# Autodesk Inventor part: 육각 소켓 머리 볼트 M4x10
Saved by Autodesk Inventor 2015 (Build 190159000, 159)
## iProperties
Created: 2024-11
Part Number: 육각 소켓 머리 볼트 M4x10
Material: 일반
Document SubType Name: Modeling
Designer: 102-5
Density: 1 g/cm^3
Appearance: 기본값
Author: 102-5
Author: jhkim
Description: 6각머리 태핑 나사
Creation Date: 2024-10-25
Sending System: Autodesk Inventor 2025
Preprocessor: ST-DEVELOPER v20
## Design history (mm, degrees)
node "육각 소켓 머리 볼트 M4x101"
body "Solid1"
node "기준1"
